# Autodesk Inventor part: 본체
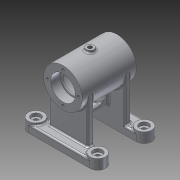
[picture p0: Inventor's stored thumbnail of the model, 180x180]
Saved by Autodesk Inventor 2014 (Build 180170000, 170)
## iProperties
Created: 2015-11
Part Number: 본체
Material: 알루미늄 6061
Document SubType Name: Modeling
Designer: basic
Density: 2.71 g/cm^3
Appearance: 알루미늄 - 평지
Mass: 359.27 g
Surface Area: 461.413 cm^2
Volume: 132.572 cm^3
Author: basic
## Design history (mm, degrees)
sketch "스케치1"
  geometry: L1 (0, 35)-(0, -35); L2 (0, 35)-(25, 35); L3 (25, -35)-(0, -35); L4 (25, 35)-(25, -35); L5 (16, 35)-(16, 23); L6 (16, 23)-(14, 23); L7 (14, 23)-(14, 21); L8 (14, 21)-(21, 21); L9 (21, 21)-(21, -21); L10 (21, -21)-(14, -21); L11 (14, -21)-(14, -23); L12 (14, -23)-(16, -23); L13 (16, -23)-(16, -35); 2 further points
  constraints: 26 end point, 8 parallel, 4 perpendicular, 2 collinear, 2 point on line, 1 coincident, 1 midpoint, 1 vertical
  dimensions: "d0" = 70 distance of L1.start L1.end; "d1" = 50 diameter of L4 L1; "d2" = 42 diameter of L9 L1; "d3" = 32 diameter of L5 L1; "d4" = 28 diameter of L7 L1; "d5" = 12 distance between parallel lines of L2 L6; "d6" = 2 distance between parallel lines of L8 L6; "d7" = 2 distance between parallel lines of L12 L10; "d8" = 12 distance between parallel lines of L3 L12
revolve "회전1" sketch "스케치1" stored, may be unused: angle "d9" = 90 deg
node "작업 평면2"
sketch "스케치5"
  geometry: L1 (-50, 40)-(50, 40); L2 (50, 40)-(50, 20); L3 (50, 20)-(-50, 20); L4 (-50, 20)-(-50, 40); 1 further point
  constraints: 8 end point, 2 parallel, 1 horizontal, 1 perpendicular
  dimensions: "d32" = 100 distance of L1.end L1.start; "d33" = 20 distance between parallel lines of L3 L1; "d34" = 40 distance from line of point (0, 0) L1; "d35" = 50 distance from line of point (0, 0) L2
extrude "돌출3" join sketch "스케치5" distance "d36" = 10; taper "d37" = 0 deg
fillet "모깎기2" dims "d38" = 10
sketch "스케치6"
  geometry: C1 r 10 at (30, 40); C2 r 10 at (30, -40); A1 r 10 centre (30, 40) between (40, 40) and (20, 40) reference; A2 r 10 centre (30, -40) between (20, -40) and (40, -40) reference; 1 further point
  constraints: 2 centre point, 2 coincident, 1 concentric
  dimensions: "d39" = 20 diameter of C1
extrude "돌출4" join sketch "스케치6" distance "d40" = 3; taper "d41" = 0 deg
sketch "스케치7"
  geometry: L1 (20, 40)-(20, -40) reference; L2 (28, -25)-(20, -25); L3 (20, -25)-(20, 25); L4 (20, 25)-(28, 25); L5 (28, 25)-(28, -25); 1 further point
  constraints: 8 end point, 2 parallel, 1 horizontal, 1 perpendicular, 1 point on line
  dimensions: "d42" = 50 distance between parallel lines of L2 L4; "d43" = 25 distance from line of point (0, 0) L4; "d44" = 8 distance between parallel lines of L1 L5
extrude "돌출5" join sketch "스케치7" stored distance "d45" = 3; taper "d46" = 0 deg
sketch "스케치9"
  geometry: L1 (-21, 21)-(-21, -21) reference; L2 (-21, -21)-(-14, -21) reference; L3 (-14, -21)-(-14, -23) reference; L4 (-14, -23)-(-16, -23) reference; L5 (-16, -23)-(-16, -35) reference; L6 (-16, -35)-(-25, -35) reference; L7 (-25, -35)-(-25, -28) reference; L8 (-25, -28)-(-58, -28) reference; L9 (-58, -28)-(-58, -40) reference; L10 (-58, -40)-(-68, -40) reference; L11 (-68, -40)-(-68, -20) reference; L12 (-68, -20)-(-25, -20) reference; L13 (-25, -20)-(-25, 20) reference; L14 (-25, 20)-(-68, 20) reference; L15 (-68, 20)-(-68, 40) reference; L16 (-68, 40)-(-58, 40) reference; L17 (-58, 40)-(-58, 28) reference; L18 (-58, 28)-(-25, 28) reference; L19 (-25, 28)-(-25, 35) reference; L20 (-25, 35)-(-16, 35) reference; L21 (-16, 35)-(-16, 23) reference; L22 (-16, 23)-(-14, 23) reference; L23 (-14, 23)-(-14, 21) reference; L24 (-14, 21)-(-21, 21) reference; L25 (25, 35)-(25, -35) reference; L26 (25, -35)-(16, -35) reference; L27 (16, -35)-(16, -23) reference; L28 (16, -23)-(14, -23) reference; L29 (14, -23)-(14, -21) reference; L30 (14, -21)-(21, -21) reference; L31 (21, -21)-(21, 21) reference; L32 (21, 21)-(14, 21) reference; L33 (14, 21)-(14, 23) reference; L34 (14, 23)-(16, 23) reference; L35 (16, 23)-(16, 35) reference; L36 (16, 35)-(25, 35) reference; L37 (-23.794, 22)-(-45, 22); L38 (-45, 22)-(-45, -22); L39 (-45, -22)-(-23.794, -22); L40 (-23.794, -22)-(-23.794, 22); 1 further point
  constraints: 8 end point, 2 parallel, 1 horizontal, 1 perpendicular
  dimensions: "d54" = 20 distance between parallel lines of L13 L38; "d55" = 22 distance from line of point (0, 0) L37; "d56" = 44 distance between parallel lines of L39 L37; "d57" = 21.20633 distance between parallel lines of L40 L38
extrude "돌출6" join sketch "스케치9" stored distance "d58" = 8; taper "d59" = 0 deg
sketch "스케치10"
  geometry: L1 (45, -20)-(45, 20) reference; L2 (35, 8)-(35, -8); L3 (31.5, 8)-(31.5, -8); L4 (38.5, -8)-(38.5, 8); L5 (25, -35)-(-25, -35) reference; L6 (68, 20)-(68, 40) reference; A1 r 3.5 centre (35, 8) between (38.5, 8) and (31.5, 8); A2 r 3.5 centre (35, -8) between (31.5, -8) and (38.5, -8); 2 further points
  constraints: 8 end point, 4 point on circle, 4 tangent, 2 centre point, 2 parallel, 1 midpoint
  dimensions: "d60" = 16 distance of L2.start L2.end; "d61" = 7 diameter of A2; "d63" = 35 distance from line of point (35, 0) L5; "d64" = 33 distance from line of L6 point (35, 0)
extrude "돌출7" cut sketch "스케치10" distance "d65" = 8; taper "d66" = 0 deg
sketch "스케치11"
  geometry: C1 r 25 at (0, 0) reference; 1 further point
  constraints: 1 horizontal alignment
  dimensions: "d67" = 20 distance of point (20, 0) C1.centre
hole "구멍1" sketch "스케치11" at (20, 0) diameter "d68" = 3.242; stored, may be unused: countersink angle "d72" = 90 deg, drill point angle "d74" = 118 deg; dims "d69" = 8, "d70" = 4, "d71" = 2, "d73" = 10
node "작업 평면4"
sketch "스케치13"
  geometry: C1 r 5 at (0, 0); 1 further point
  constraints: 1 centre point, 1 coincident
  dimensions: "d79" = 10 diameter of C1
extrude "돌출8" join sketch "스케치13" stored distance "d80" = 8; taper "d81" = 0 deg
sketch "스케치14"
  geometry: C1 r 5 at (0, 0) reference; 1 further point
  constraints: 1 coincident
hole "구멍2" sketch "스케치14" at (0, 0) diameter "d82" = 5.188; stored, may be unused: countersink angle "d86" = 90 deg, drill point angle "d88" = 118 deg; dims "d83" = 8, "d84" = 4, "d85" = 2, "d87" = 10
sketch "스케치18"
  geometry: C1 r 10 at (0, 0) reference; 2 further points
  constraints: 1 coincident
hole "구멍4" sketch "스케치18" at (0, 0) diameter "d102" = 6; stored, may be unused: countersink angle "d106" = 90 deg, drill point angle "d108" = 118 deg; dims "d103" = 8, "d104" = 12, "d105" = 4, "d107" = 10
node "작업 평면9"
fillet "모깎기3" dims "d113" = 0.3
fillet "모깎기4" dims "d114" = 0.3
fillet "모깎기5" dims "d115" = 2
fillet "모깎기6" dims "d116" = 2
fillet "모깎기7" dims "d117" = 2
fillet "모깎기8" dims "d118" = 2
fillet "모깎기9" dims "d119" = 3
fillet "모깎기10" dims "d120" = 2
sketch "스케치21"
  geometry: L1 (25, 35)-(25, -35) reference; L2 (-25, -35)-(25, -35) reference; 2 further points
  constraints: 1 coincident, 1 other
  dimensions: "d121" = 35 distance from line of L2 point (0, 0) (derived); "d122" = 25 distance from line of L1 point (0, 0) (derived)
feature "엠보싱1" sketch "스케치21" dims "d0" = 70, "d1" = 50, "d2" = 42, "d3" = 32, "d4" = 28, "d5" = 12, "d6" = 2, "d7" = 2, "d8" = 12, "d32" = 100, "d33" = 20, "d34" = 40, "d35" = 50, "d123" = 0.5, "d124" = 0
node "작업 평면13"
  node "작업 평면12"
sketch "스케치22"
  geometry: C1 r 6 at (0, 0); 1 further point
  constraints: 1 centre point, 1 coincident
  dimensions: "d128" = 12 diameter of C1
extrude "돌출10" join sketch "스케치22" stored distance "d129" = 8; taper "d130" = 0 deg
sketch "스케치23"
  geometry: C1 r 6 at (0, 0) reference; 1 further point
  constraints: 1 coincident
hole "구멍5" sketch "스케치23" at (0, 0) diameter "d131" = 5.188; stored, may be unused: countersink angle "d135" = 90 deg, drill point angle "d137" = 118 deg; dims "d132" = 8, "d133" = 12, "d134" = 4, "d136" = 10
node "솔리드1"
mirror "대칭2"
pattern_circular "원형 패턴1" dims angle "d76" = 360 deg
mirror "대칭3"
mirror "대칭4"
mirror "대칭5"
mirror "대칭6"
node "절단 모서리 투영2"
other parameters: "d29" = 68, "d78" = -28, "d126" = 30 deg, "d127" = 28
